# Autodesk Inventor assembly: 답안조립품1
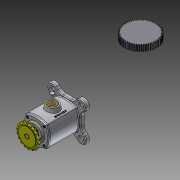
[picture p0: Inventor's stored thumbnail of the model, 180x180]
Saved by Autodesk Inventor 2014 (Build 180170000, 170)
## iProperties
Created: 2016-05
Part Number: 답안조립품1
Document SubType Name: Assembly
Designer: Administrator
Author: Administrator
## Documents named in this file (12)
- C:\Users\Administrator\Desktop\460507V1015\답안조립품.iam
- C:\Users\Administrator\Desktop\460507V1015\본체.ipt
- C:\Users\Administrator\Desktop\460507V1015\M4x0.7x12.ipt
- C:\Users\Administrator\Desktop\460507V1015\베어링-6203.ipt
- C:\Users\Administrator\Desktop\460507V1015\부시.ipt
- C:\Users\Administrator\Desktop\460507V1015\스퍼기어.ipt
- C:\Users\Administrator\Desktop\460507V1015\스프로킷.ipt
- C:\Users\Administrator\Desktop\460507V1015\슬라이더.ipt
- C:\Users\Administrator\Desktop\460507V1015\오일실.ipt
- C:\Users\Administrator\Desktop\460507V1015\커버.ipt
- C:\Users\Administrator\Desktop\460507V1015\키5x5.ipt
- C:\Users\Administrator\Desktop\460507V1015\편심축.ipt
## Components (8 placed, 1 different names)
1. M4x0.7x12:2
2. M4x0.7x12:3
3. M4x0.7x12:4
4. M4x0.7x12:5
5. M4x0.7x12:1
6. M4x0.7x12:6
7. M4x0.7x12:7
8. M4x0.7x12:8
